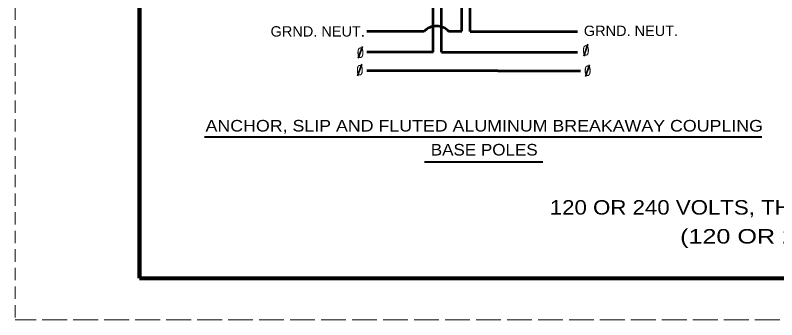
# Model space of a CAD drawing. Extents: x -153 to 527, y -247 to 194.
# Drawn here: x -153.1 to 31.2, y -246.5 to -172.9 of the extents above; entities that cross this region are included whole.
import ezdxf
from ezdxf.enums import TextEntityAlignment as Align

# ---------------------------------------------------------------- set-up
doc = ezdxf.new("R2010")
doc.units = 0
doc.linetypes.add('LONG_DASHED', pattern=[7.5, 6, -1.5])
doc.linetypes.add('MEDIUM_DASHED', pattern=[4.5, 3, -1.5])
doc.layers.add('1', color=7, linetype='Continuous', lineweight=53)
doc.layers.add('61', color=7, linetype='Continuous', lineweight=35)

msp = doc.modelspace()

# ---------------------------------------------------------------- linework, layer by layer
at = {"layer": '1', "linetype": 'MEDIUM_DASHED', "lineweight": 13}
msp.add_line((-153.062, 193.509), (-153.122, -246.531), dxfattribs=at)
at = {"layer": '1'}
for p, q in [((-51.968, -181.835), (-51.968, -136.098)), ((-49.968, -181.835), (-49.968, -136.098)), ((-44.968, -176.707), (-44.968, -136.206)), ((-42.968, -176.835), (-42.968, -136.098)), ((-54.152, -176.779), (-68.033, -176.779)), ((-48.223, -176.707), (-44.968, -176.707)), ((-42.968, -176.835), (-16.968, -176.835)), ((-51.968, -181.835), (-67.968, -181.835)), ((-36.308, -186.336), (-67.968, -186.336)), ((-36.308, -186.336), (-16.308, -186.336))]:
    msp.add_line(p, q, dxfattribs=at)
at = {"layer": '1', "lineweight": 35}
for p, q in [((-69.036, -180.426), (-70.067, -183.259)), ((-14.468, -179.9), (-15.499, -182.732)), ((-69.198, -184.68), (-70.229, -187.513)), ((-14.063, -184.842), (-15.095, -187.675))]:
    msp.add_line(p, q, dxfattribs=at)
at = {"layer": '1', "lineweight": 40}
for p, q in [((-107.308, -202.256), (27.653, -202.256)), ((-54.008, -208.368), (-25.402, -208.368))]:
    msp.add_line(p, q, dxfattribs=at)
at = {"layer": '1'}
msp.add_lwpolyline([(-49.968, -181.835), (-41.964, -181.835), (-16.968, -181.835)], dxfattribs=at)
msp.add_arc((-51.152, -179.707), 4.193, 44.3118, 135.68821, dxfattribs=at)
at = {"layer": '61', "lineweight": 158}
msp.add_line((515.998, -236.531), (-123.062, -236.511), dxfattribs=at)
at = {"layer": '61', "linetype": 'LONG_DASHED', "lineweight": 13}
msp.add_line((526.938, -246.511), (-153.122, -246.531), dxfattribs=at)
at = {"layer": '61', "lineweight": 158}
msp.add_lwpolyline([(515.978, 183.509), (-123.062, 183.509), (-123.062, -236.511)], dxfattribs=at)

# ---------------------------------------------------------------- texts
at = {"layer": '1'}
for s, width, p in [('GRND. NEUT.', 1.05, (-91.299, -178.031)), ('GRND. NEUT.', 1.05, (-15.465, -177.89)), ('0', 0.9, (-70.389, -183.185)), ('0', 0.9, (-15.801, -182.623)), ('0', 0.9, (-70.53, -187.406)), ('0', 0.9, (-15.378, -187.547))]:
    msp.add_text(s, height=2.5, dxfattribs=dict(at, width=width)).set_placement(p)
for s, height, width, p in [('ANCHOR, SLIP AND FLUTED ALUMINUM BREAKAWAY COUPLING', 2.8, 1.15, (-39.583, -201)), ('BASE POLES', 2.8, 1.1, (-39.583, -206.8)), ('120 OR 240 VOLTS, THREE WIRE, GROUNDED NEUTRAL', 3.5, 1.15, (49.26, -221.097)), ('(120 OR 240 VOLT BALLAST)', 3.5, 1.3, (49.26, -228.097))]:
    msp.add_text(s, height=height, dxfattribs=dict(at, width=width)).set_placement(p, align=Align.CENTER)

doc.saveas('drawing.dxf')
